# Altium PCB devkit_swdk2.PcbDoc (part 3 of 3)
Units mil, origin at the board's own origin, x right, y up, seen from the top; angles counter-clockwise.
Board outline 2700 x 2100 mil, 4 copper layers (Component Side, Internal Plane 1, Internal Layer 2, Bottom Layer), stack 57.8 mil thick; 223 components, 143 nets, 656 pads, 485 vias.
Unrouted connection lines stored in the file: 72.
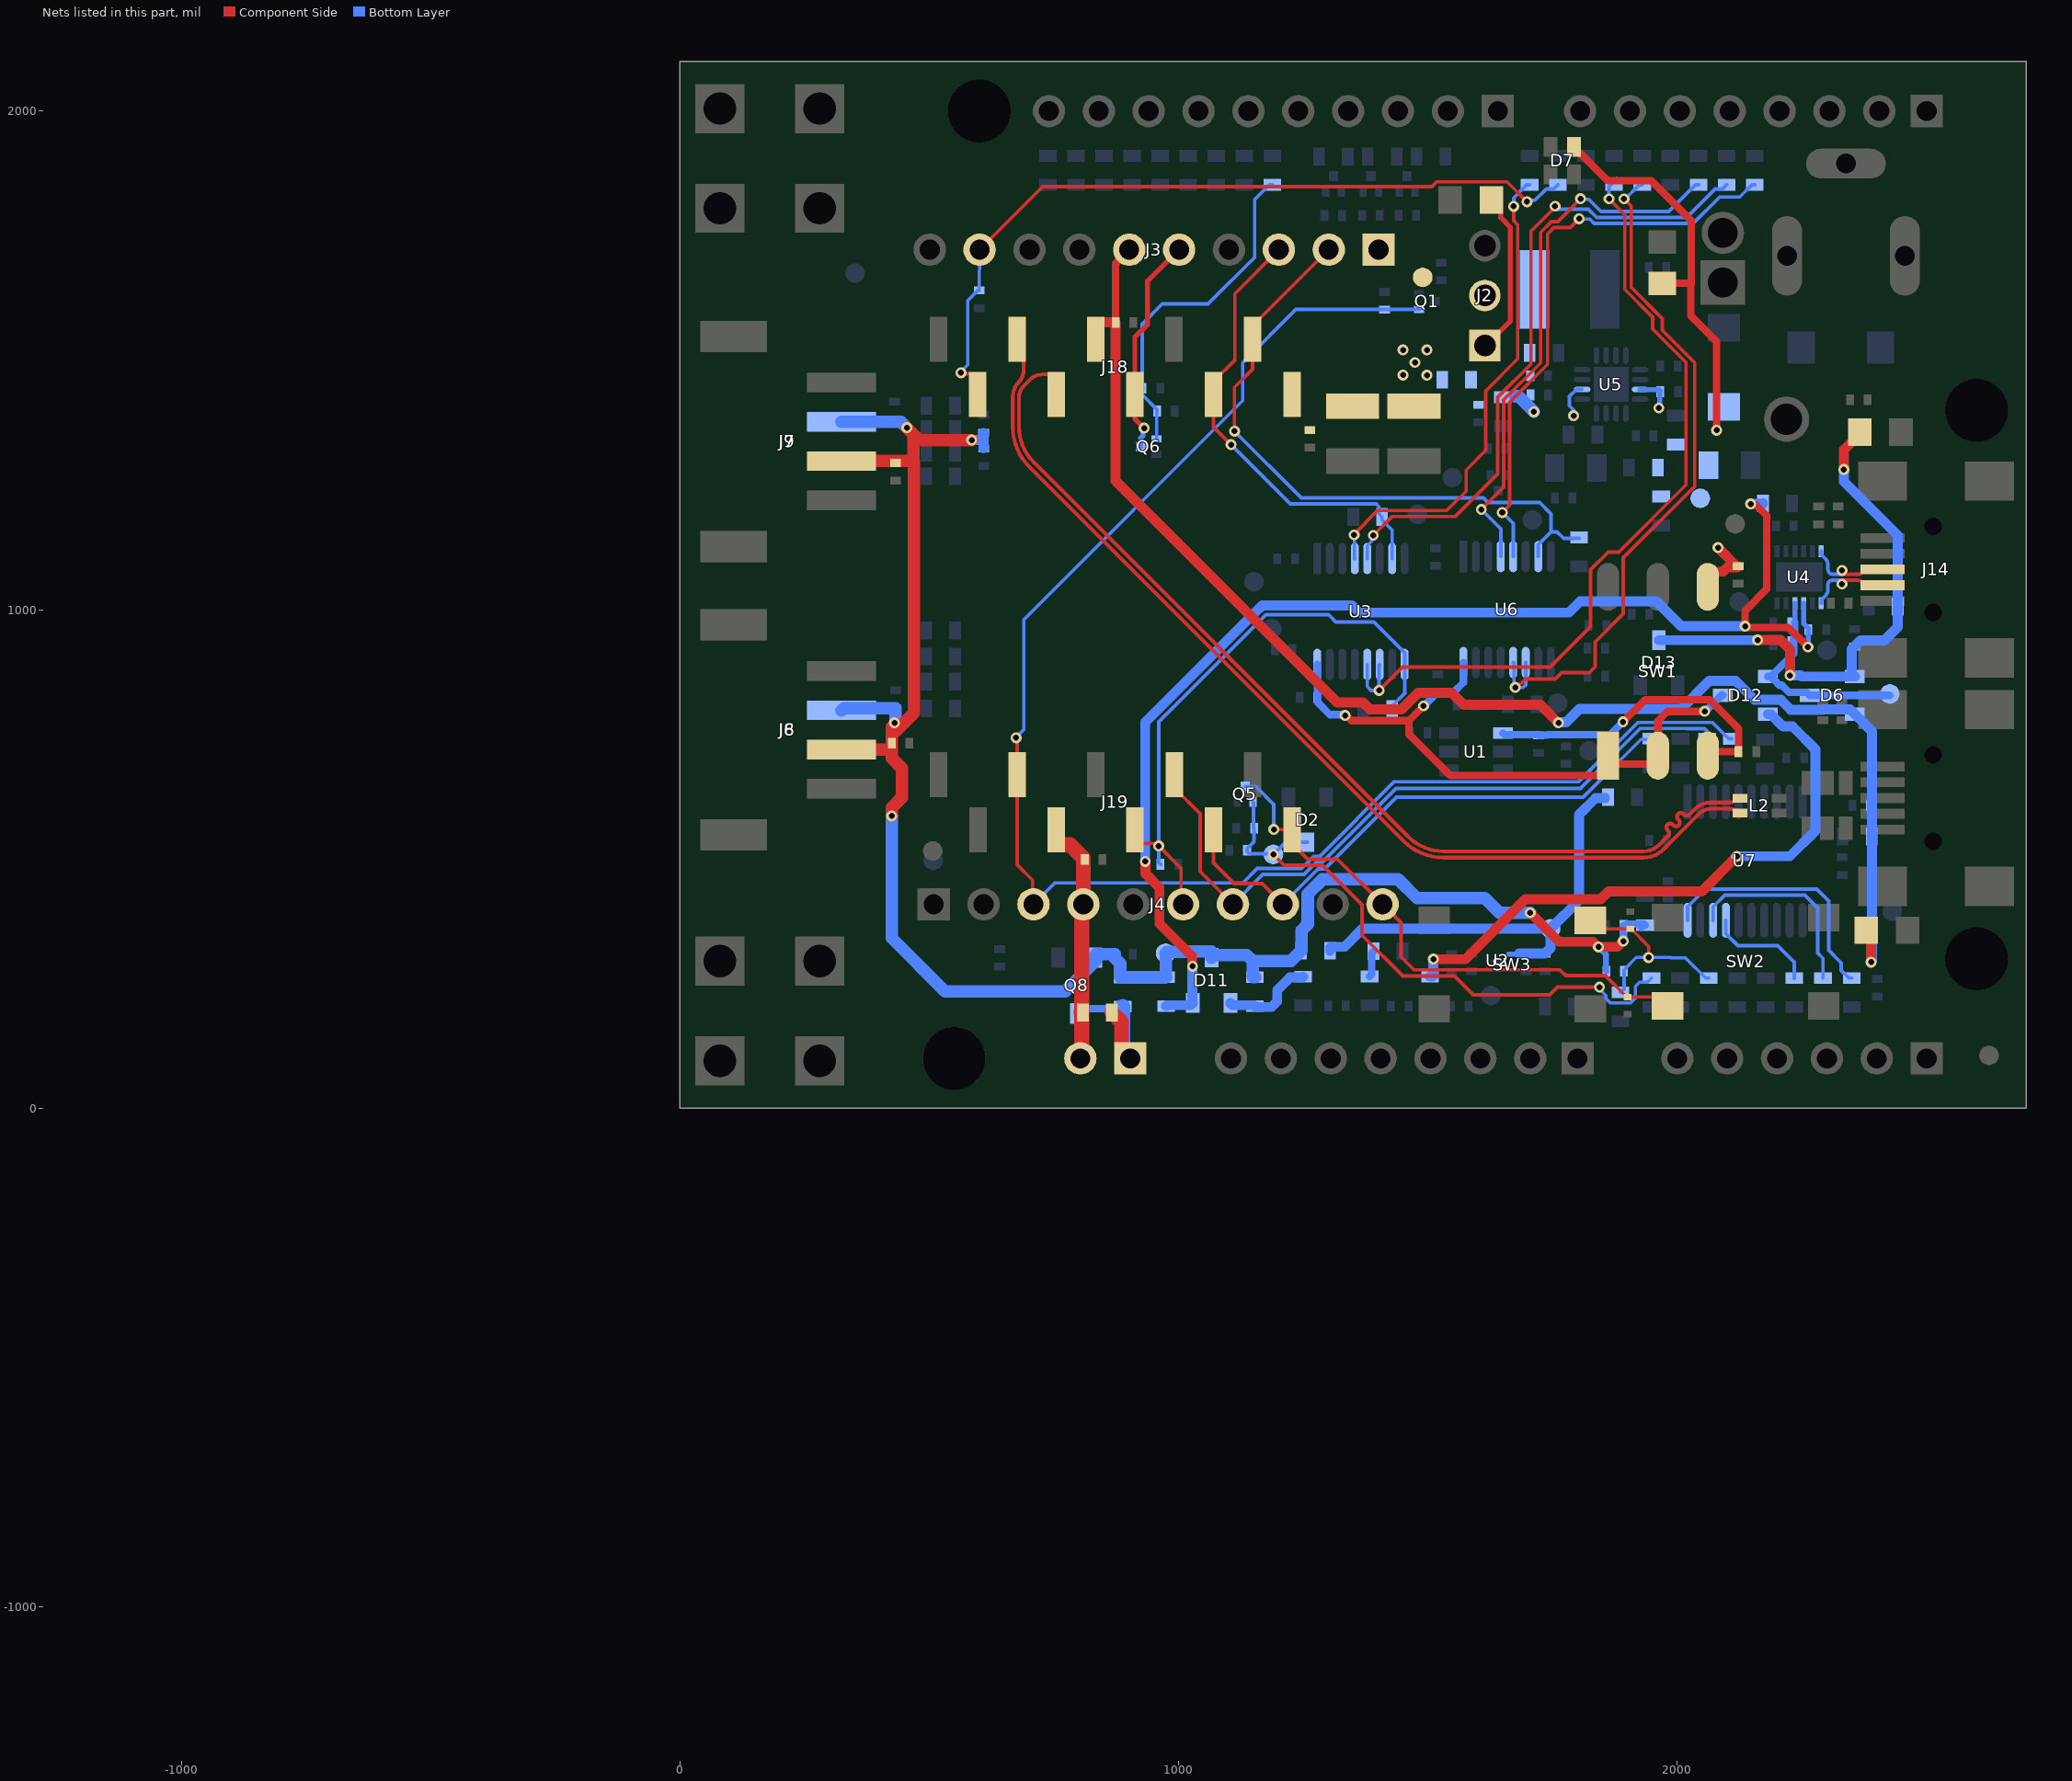
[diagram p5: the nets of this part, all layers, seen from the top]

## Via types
v1: diameter 22, hole 12, Component Side to Bottom Layer, 485 vias

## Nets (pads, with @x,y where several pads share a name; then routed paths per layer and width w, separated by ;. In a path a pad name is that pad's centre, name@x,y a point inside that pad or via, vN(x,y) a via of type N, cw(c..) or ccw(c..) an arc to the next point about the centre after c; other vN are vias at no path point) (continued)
SKY_CTS_ARD: SB19.2 U6.11 U6.12 | length 1425.2
  Component Side w7: v1(1675,844) 1678.41,844 1695.41,861 1755.02,861 1768.02,874 1823.58,874 1835,885.42 1835,935 1891.74,991.74 1891.74,1104.24 2035,1247.5 2035,1495.42 1970,1560.42 1970,1584 1907.5,1646.5 1907.5,1809.5 v1(1893,1824)
  Bottom Layer w7: U6.12@1671,893.92 1672.67,892.25 1672.67,846.33 v1(1675,844) 1691,844 1696,849 U6.11@1696,893.92 ; v1(1893,1824) 1895.73,1824 1923.74,1852.01 SB19.2@1929.64,1852.01
SKY_DIN: J3.3 J18.3 SB48.1 U3.7 | length 923.2
  Component Side w7: v1(1105,1331) 1069.83,1366.17 J18.3@1069.83,1431.81 1069.83,1457.83 1113,1501 1113,1634 J3.3@1201,1722
  Bottom Layer w7: v1(1105,1331) 1223.78,1212.22 1396.34,1212.22 1401.39,1207.17 1401.39,1192.61 SB48.1@1408,1186 1408,1180.09 1428.25,1159.84 U3.7@1428.25,1102.68
SKY_DIO2: J4.8 J19.8 SB45.1 | length 1130.9
  Component Side w7: J19.8@1070,558.74 1070,492 1111.5,450.5 1167.5,450.5 J4.8@1209,409
  Bottom Layer w7: J4.8@1209,390 1209,390.41 J4.8@1218.3,399.7 ; J4.8@1209,409 1209,409.41 1279.59,480 1293,480 1437,624 1811.42,624 1926.92,739.5 1946.23,739.5 SB45.1@1948.25,741.52
SKY_DIO2_VREF: SB29.1 U7.20 | length 511.9
  Bottom Layer w7: U7.20@2020.6,377 2020.6,404 2056.2,439.6 2279.45,439.6 2303.5,415.55 2303.5,316.77 2328.78,291.49 2328.78,276.31 2344.09,261 SB29.1@2350,261
SKY_DIO3: J4.7 J19.7 SB46.1 | length 1456.7
  Component Side w7: J19.7@991.26,668.98 991.26,642.74 1043,591 1043,475 J4.7@1109,409 J4.7@1109,390
  Bottom Layer w7: J4.7@1109,409 1168.81,468.81 1251.44,468.81 1274.62,492 1286.5,492 1436,641.5 1805.5,641.5 1925.83,761.83 2018.63,761.83 2019.15,761.31 2054.73,761.31 2063.63,752.41 SB46.1@2063.63,741 ; SB46.1@2059.58,741 SB46.1@2063.63,741 ; SB46.1@2063.63,732.17 SB46.1@2063.63,741
SKY_DIO3_VREF: SB28.1 U7.18 | length 402.5
  Bottom Layer w7: U7.18@2071.8,377 2071.8,404 2095.4,427.6 2255.9,427.6 2281.5,402 2281.5,311.5 2292.25,300.75 SB28.1@2292.25,261
SKY_DOUT: J3.2 J18.2 SB49.1 U6.7 | length 1276.7
  Component Side w7: v1(1112,1358) 1112,1446 1148.57,1482.57 J18.2@1148.57,1542.05 ; J18.2@1148.57,1569.61 J3.2@1301,1722
  Bottom Layer w7: v1(1112,1358) 1245.78,1224.22 1611.36,1224.22 1620.58,1215 1724,1215 1747,1192 1747,1156.14 ; U6.7@1721,1106.52 1721,1130.14 1747,1156.14 ; SB49.1@1803.5,1143 1772.14,1143 1759,1156.14 1747,1156.14
SKY_DTR: J3.9 J18.9 R6.2 SB16.2 | length 1580.2
  Component Side w7: v1(563.5,1475) 565.11,1473.39 583.37,1473.39 597.39,1459.37 J18.9@597.39,1431.81 ; J3.9@601,1722 727.5,1848.5 1507.81,1848.5 1517.37,1858.06 1658.64,1858.06 v1(1698.51,1818.19)
  Bottom Layer w7: v1@563.5,1477.5 577,1491 577,1619.97 597.2,1640.18 R6.2@600.15,1640.18 J3.9@601,1722 ; v1(1698.51,1818.19) 1701.38,1821.06 1714.61,1821.06 1737.24,1843.7 1752.1,1843.7 SB16.2@1760.41,1852.01 ; J3.9@601,1722 ccw(c603.04,1719.96) 600.15,1719.96 cw(c603.04,1719.96) J3.9@601,1722
SKY_NRESET: J3.5 J18.5 Q6.3 | length 442.8
  Component Side w10: v1(931,1364) 912.35,1382.65 J18.5@912.35,1431.81 912.35,1546.48 938,1572.14 938,1659 J3.5@1001,1722
  Bottom Layer w10: Q6.3@924.25,1327 923.63,1327.63 923.63,1344 928.7,1349.08 928.7,1361.7 v1(931,1364)
Sky_ON_OFF_SW: C40.1 D2.3 Q5.1 R56.2 SB24.1 TP7.1 | length 1212.3
  Component Side w7: v1(1190,509) 1211.5,487.5 1288.48,487.5 1368,407.98 1368,347 1450,265 1553.11,265 1590.61,227.5 1744.08,227.5 1759.58,243 v1(1844,243)
  Bottom Layer w7: Q5.1@1149,614 1150.09,612.91 1150.09,562.84 R56.2@1151.18,561.75 1151.18,534.53 1137.26,520.61 C40.1@1137.26,517.65 1137.26,514.7 1141.63,510.33 1182.33,510.33 1185.5,513.5 v1(1190,509) 1214.45,533.45 D2.3@1258.21,533.45 ; v1(1844,243) 1844,238.94 1856.77,226.17 1856.77,220.18 1865.5,211.45 1906.5,211.45 1916,220.95 1916,244.5 1924.19,252.69 1939.94,252.69 SB24.1@1948.25,261
SKY_ONOFF: D14.K J4.10 J19.10 Q5.3 SW2.2 | length 1115.1
  Component Side w7: v1(1191,559) 1227.22,559 J19.10@1227.48,558.74 1227.48,531.18 1259.16,499.5 1318.5,499.5 J4.10@1409,409 1445.9,372.1 1445.9,303.52 1471.7,277.72 1764.39,277.72 1776,266.12 1855.63,266.12 1898.52,223.22 1962.7,223.22 SW2.2@1980.5,205.42
  Bottom Layer w7: Q5.3@1133.25,645.5 1154.5,645.5 1191,609 v1(1191,559)
SKY_ONSLEEP: J4.3 J19.3 Q1.1 R23.2 SB47.1 | length 3269.9
  Component Side w7: v1(674,743) 676.3,740.7 J19.3@676.3,668.98 676.3,488.2 707,457.5 707,392 J4.3@709,390
  Bottom Layer w7: v1@674,744 689.5,759.5 689.5,980.05 1128.52,1419.07 1128.52,1495.52 1235.25,1602.25 Q1.1@1482.25,1602.25 ; J4.3@709,409 752,452 1129,452 1157.81,480.81 1246.46,480.81 1270.91,505.26 1282.79,505.26 1432.53,655 1802.03,655 1920.86,773.83 2070.27,773.83 2103.09,741 SB47.1@2109,741
SKY_ONSLEEP_VREF: SB27.1 U7.17 | length 219.8
  Bottom Layer w7.55: U7.17@2097.4,377 2097.4,350 2121.56,325.84 2201.66,325.84 2234.75,292.75 SB27.1@2234.75,261
SKY_RESET: C47.1 Q6.1 R21.2 SB14.2 | length 688.3
  Bottom Layer w7: R21.2@927.82,1444.15 927.5,1443.83 R21.2@927.5,1443.65 ; Q6.1@955.75,1342.75 956.25,1343.25 956.25,1397.85 C47.1@956.74,1398.35 956.74,1401.3 927.5,1430.54 R21.2@927.5,1443.65 ; SB14.2@1188,1852.19 1182.09,1852.19 1152.5,1822.6 1152.5,1706.5 1059.15,1613.15 967.15,1613.15 927,1573 927,1444.15 R21.2@927.5,1443.65
SKY_RTS: J4.6 J19.6 R7.2 SB50.1 U3.9 | length 1264.2
  Component Side w7: J19.6@912.52,558.74 912.52,531.18 954.82,531.18 v1(960,526) 1004.87,481.13 1004.87,394.13 J4.6@1009,390
  Bottom Layer w7: R7.2@963.82,489.15 960,492.98 v1(960,526) 960,774.95 1160.55,975.5 1160.77,975.5 1175.33,990.05 1300.95,990.05 1315.5,975.5 1391.46,975.5 1453.25,913.71 U3.9@1453.25,890.08 1453.25,832.01 1428.15,806.91 SB50.1@1428.15,801 ; J4.6@1004.55,394.45 J4.6@1009,390
SKY_RTS_ARD: SB18.2 U3.11 U3.12 | length 1661.1
  Component Side w7: v1(1402,838) 1449,885 1745.08,885 1826,965.92 1826,1080.1 1861.4,1115.5 1882.58,1115.5 2017.5,1250.42 2017.5,1495.95 1950.5,1562.95 1950.5,1586.53 1894.81,1642.22 1894.81,1792.19 v1(1863,1824)
  Bottom Layer w7: U3.12@1378.25,890.08 1378.25,845.75 1386,838 v1(1402,838) 1402,888.83 U3.11@1403.25,890.08 ; v1(1863,1824) 1863,1848.5 1878.5,1864
SKY_USB_N: J18.8 L2.2 | length 2244.6
  Component Side w7.6: J18.8@689,1498 689,1478.64 ; 1451.51,535.67 700.35,1286.83 ; L2.2@2125.63,592.43 L2.2@2125.63,592.43 cw(c2125.57,606.54) 2115.59,596.57 ccw(c2105.61,586.59) 2105.61,600.7 2067.42,600.7 ccw(c2067.42,567.58) 2044,591 1987.5,534.5 1972.19,519.19 cw(c1932.38,558.99) 1932.38,502.7 1531.08,502.7 ; 667.4,1366.38 ccw(c779.9,1366.38) 700.35,1286.83 ; 667.4,1366.38 ccw(c779.9,1366.38) 700.35,1286.83 ; 667.4,1366.38 667.4,1426.49 ; 667.4,1426.49 cw(c711.2,1426.49) 680.23,1457.46 ; 667.4,1426.49 cw(c711.2,1426.49) 680.23,1457.46 ; 680.23,1457.46 ccw(c659.05,1478.64) 689,1478.64 ; 680.23,1457.46 ccw(c659.05,1478.64) 689,1478.64 ; 1531.08,502.7 cw(c1531.08,615.2) 1451.53,535.65 ccw(c1531.08,615.2) 1531.08,502.7
SKY_USB_P: J18.7 L2.1 | length 2239.9
  Component Side w7.6: J18.7@744.03,1457.97 744.03,1469.11 741.15,1472 728,1472 ; L2.1@2125.63,621.57 L2.1@2125.63,621.57 ccw(c2125.57,607.46) 2115.59,617.43 cw(c2105.61,627.41) 2105.61,613.3 2067.37,613.3 ccw(c2067.37,567.7) 2035.06,599.88 2029.69,594.51 2024.31,589.13 cw(c2018.94,594.51) 2013.56,589.13 2012.47,590.22 ccw(c2007.1,584.85) 2001.72,590.22 ccw(c2007.1,584.85) 2001.72,579.47 2002.82,578.38 cw(c1997.44,573.01) 2002.82,567.64 cw(c1997.44,573.01) 1992.07,567.64 1990.98,568.73 ccw(c1985.6,563.35) 1980.23,568.73 ccw(c1985.6,563.35) 1980.23,557.98 1981.32,556.89 cw(c1975.95,551.51) 1981.32,546.14 1978.59,543.41 1963.38,528.2 cw(c1932.24,559.34) 1932.24,515.3 1531.12,515.3 ; 680,1366.42 ccw(c780,1366.42) 709.29,1295.71 ; 680,1366.42 ccw(c780,1366.42) 709.29,1295.71 ; 680,1366.42 680,1426.47 cw(c711.26,1426.47) 689.16,1448.57 701.69,1461.1 ; 701.69,1461.1 cw(c728,1434.79) 728,1472 ; 701.69,1461.1 cw(c728,1434.79) 728,1472 ; 709.29,1295.71 1460.41,544.59 ; 1460.41,544.59 ccw(c1531.12,615.3) 1531.12,515.3 ; 1460.41,544.59 ccw(c1531.12,615.3) 1531.12,515.3
SKY_VREF: C24.1 J1.2 J4.4 J19.4 R3.1 | length 498.2
  Component Side w30: J19.4@755.04,558.74 755.04,531.18 757.56,528.66 782.23,528.66 809,501.9 809,409.26 808.74,409 808.74,390.26 809,390 806,387 806,103 J1.2@803,100
UART_RX1: SB23.2 U6.5 | length 1157.9
  Component Side w7: v1(1649,1195) 1664,1210 1664,1416.06 1739.85,1491.91 1739.85,1753.68 1752.53,1766.36 1785.36,1766.36 v1(1803,1784)
  Bottom Layer w7: v1(1649,1195) 1671,1173 U6.5@1671,1106.52 ; v1(1803,1784) 1803.47,1783.53 1824.5,1783.53 1833.53,1774.5 2031.87,1774.5 2085.19,1827.81 2125.19,1827.81 2149.38,1852.01 SB23.2@2155.28,1852.01
UART_RX2: SB21.2 U6.4 | length 1092.4
  Component Side w7: v1(1607,1201) 1652,1246 1652,1421.03 1725.83,1494.86 1725.83,1756.64 1747.7,1778.5 1760.43,1778.5 v1(1806.13,1824.2)
  Bottom Layer w7: v1(1607,1201) 1646,1162 U6.4@1646,1106.52 ; v1@1806.13,1823 1822.36,1823 1846.86,1798.5 1983.05,1798.5 2036.56,1852.01 SB21.2@2042.46,1852.01
UART_TX1: SB22.2 U3.5 | length 1317.1
  Component Side w7: v1(1390.36,1149) 1428.36,1187 1555,1187 1640,1272 1640,1426 1706.5,1492.5 1706.5,1758.92 1755,1807.42 v1(1755,1809.19)
  Bottom Layer w7: U3.5@1378.25,1102.68 1378.25,1128.67 1387.49,1137.91 1387.49,1146.13 v1(1390.36,1149) ; v1(1755,1809.19) 1760.69,1803.5 1821.5,1803.5 1838.5,1786.5 2018.5,1786.5 2075.7,1843.7 2090.56,1843.7 SB22.2@2098.87,1852.01
UART_TX2: SB15.2 U3.4 | length 986.9
  Component Side w7: v1(1352,1150) 1352,1151.58 1399.42,1199 1538,1199 1576.5,1237.5 1576.5,1280 1616,1319.5 1616,1437.97 1618,1439.97 1618,1441 1680,1503 1680,1772 1672,1780 v1(1672,1809)
  Bottom Layer w7: v1(1352,1150) 1352.63,1149.37 1352.63,1103.31 U3.4@1353.25,1102.68 ; v1(1672,1809) 1672,1825.91 1698.09,1852.01 SB15.2@1704,1852.01
USB_N: J14.2 U4.1 | length 173.6
  Component Side w7: v1(2330,1051.3) 2330,1058 2330.87,1058.87 2360.34,1058.87 cw(c2360.34,1042.23) 2366.35,1057.74 cw(c2360.34,1042.23) 2372.11,1053.99 ccw(c2383.88,1065.76) 2383.88,1049.12 J14.2@2411.43,1049.12
  Bottom Layer w7: U4.1@2288.72,1012.83 2288.72,1019.72 2297.06,1028.06 ccw(c2285.12,1040) 2302,1040 2302,1050 cw(c2311,1050) 2311,1059 2329.47,1059 2330,1058.47 v1(2330,1051.3)
USB_P: J14.3 U4.12 | length 171.3
  Component Side w7: v1(2330,1078.55) 2330,1072 2331.13,1070.87 2360.34,1070.87 ccw(c2360.34,1087.51) 2366.35,1071.99 ccw(c2360.34,1087.51) 2372.11,1075.74 cw(c2383.88,1063.97) 2383.88,1080.61 J14.3@2411.43,1080.61
  Bottom Layer w7: U4.12@2288.72,1117.17 2288.72,1110.28 2297.07,1101.93 cw(c2285.12,1090) 2302,1090 ; 2302,1088 2302,1081 ccw(c2312,1081) 2312,1071 2330,1071 v1(2330,1078.55)
User_Button: C39.1 D15.K R32.2 SB53.1 SW3.2 | length 406
  Component Side w7: SW3.2@1825.5,376.58 1842.3,359.78 1907.48,359.78 1942.5,324.75 v1(1942.5,302.5)
  Bottom Layer w7: C39.1@1886,232.5 1893.18,239.68 R32.2@1893.18,274.85 1893.18,277.8 1917.88,302.5 v1(1942.5,302.5) 1986.58,302.5 1987.58,301.5 2016.34,301.5 2056.84,261 SB53.1@2062.75,261
VCC_1V8: C37.1 C38.1 SB31.1 SB43.1 TP11.1 U2.1 | length 902.8
  Bottom Layer w10: U2.1@1661.06,308.8 1681.54,308.8 1683,310.26
  Bottom Layer w20: SB31.1@1303.63,316 1303.63,321.91 SB31.1@1303.73,322 ; SB31.1@1303.63,322.09 SB31.1@1303.73,322 ; SB31.1@1305.44,320.28 SB31.1@1303.73,322 ; 1683,310.26 C37.1@1696.85,310.26 C38.1@1734.85,310.26 1746,321.41 TP11.1@1746,360 1803,417 1803,589.11 1835.59,621.69 1835.59,622 SB43.1@1855,622 ; TP11.1@1734.92,360 1368.84,360 1332.55,323.72 1305.44,323.72 SB31.1@1303.73,322
VCC_3V3_FTDI: C16.1 D11.2 SB1.1 SB32.1 U4.3 | length 2534.7
  Component Side w15: v1(2147,1212) 2148.34,1210.66 2157.57,1210.66 2179.5,1188.73 2179.5,1041.27 2135.88,997.65 v1(2135.88,966.8) 2138.18,964.5 2222.5,964.5 2260,927 v1@2261,927
  Component Side w20: v1(933,495) 933.38,494.62 933.38,470.62 961.5,442.5 961.5,370.32 1027,304.82 v1@1027,286
  Bottom Layer w10: U4.3@2253.28,1012.83 2253.28,972.26 2262.3,963.24 C16.1@2262.3,954.39 ; v1(2262,925) 2262.37,925.37 2262.37,954.02 C16.1@2262.52,954.17
  Bottom Layer w20: v1(933,495) 933,774.12 1152.88,994 1153.11,994 1167.66,1008.55 1347.45,1008.55 1362,994 1453.74,994 1473.77,994 1782.68,994 1805.35,1016.67 1957.76,1016.67 2007.64,966.8 v1(2135.88,966.8) ; SB32.1@975,205 976.81,206.81 1024.42,206.81 1028.2,210.59 D11.2@1028.2,211.45 1027.38,212.27 v1@1027.38,285.62 ; v1(2147,1212) 2147.38,1212.38 2171.38,1212.38 SB1.1@2172,1213
  other v1: 1028,285
VCC_4V0: C9.1 C10.1 C11.1 C22.1 C43.1 C44.1 D1.1 J2.1 L1.2 R4.1 R33.2 SW1.4 U5.7 U5.14 | length 675.7
  Component Side w10: J2.1@1616,1529 1665,1578 1665,1767 1645.81,1786.19 1645.81,1803.38 D1.1@1627.18,1822
  Component Side w20: SW1.4@2061,1045.83 2061,1064.99 2072.31,1076.31 2091.47,1076.31 2100.3,1085.13 2121.33,1085.13 2122.15,1085.96 C43.1@2122.15,1087.26 2118.74,1087.26 v1(2081.5,1124.5)
  Bottom Layer w7: v1(1792,1389) 1792,1400.87 1783.89,1408.98 1783.89,1427.8 1797.77,1441.69 U5.14@1809.12,1441.69
  Bottom Layer w10: U5.7@1925.26,1441.69 1925.46,1441.49 1963.13,1441.49 1966,1438.62 R33.2@1966,1437.15 1964.5,1435.65 1964.5,1406 v1(1963,1404.5)
  Bottom Layer w25: 1675.5,1428 1681.5,1428 v1(1712.5,1397)
VCC_4V0_Modem: C1.1 C2.1 C3.1 J2.2 J3.1 J18.1 R4.2 TP14.1
  other v1: 1450,1470.5 1498,1470 1474,1495.75 1450,1521 1498,1521
VCC_5V0_MUX: C41.1 C42.1 D12.3 SW1.1 SW1.2 U3.16 U6.16 | length 1262.9
  Component Side w15: v1(1334,788) 1335.89,788 1346.39,777.5 1461.5,777.5 ; v1(1491,807) 1461.5,777.5 ; v1(2055,796) 1980.5,796 1961,776.5 SW1.2@1961,707.25 1961,703.62 1947.38,690 1861,690 1861,681.74 1846.26,667 1545.06,667 1461.5,750.56 1461.5,777.5
  Bottom Layer w15: U3.16@1278.25,890.08 1278.25,814.75 1303.66,789.34 1332.66,789.34 v1(1334,788) ; v1(1491,807) 1491,806.37 1491.21,806.16 C42.1@1519.47,834.43 ; C42.1@1519.85,834.8 C42.1@1519.47,834.43 ; U6.16@1571,893.92 1571,854 1551.43,834.43 C42.1@1519.47,834.43 ; v1(2055,796) 2056.8,796 2090,829.2 D12.3@2091,828.2
VCC_ARD_3V3: SB3.1 SB42.1 | length 53.7
  Bottom Layer w15: SB3.1@1383.03,264.57 1387.02,268.56 1387.02,311.02 SB42.1@1391,315
VCC_ARD_5V0: D12.2 SB4.1 | length 1198
  Component Side w20: v1(1511,299) 1575.23,299 1695.37,419.14 1846.14,419.14 1862,435 2049,435 v1(2119.5,505.5)
  Bottom Layer w20: SB4.1@1504,264.57 1508.81,264.57 1510.62,266.38 1510.62,298.62 v1(1511,299) ; v1(2119.5,505.5) 2225.82,505.5 2277.05,556.73 2277.05,719.89 2231.32,765.62 2212.38,765.62 2212,766 ; D12.2@2181.55,790.41 2187.46,790.41 2209.87,768 2210,768
VCC_ARD_IOREF: D11.1 SB2.1 SB33.1 | length 188.1
  Bottom Layer w20: D11.1@1103.8,211.45 1103.8,210.47 1107.58,206.69 1151.19,206.69 SB33.1@1153,204.88 1154.81,203.07 1186.06,203.07 1197.78,214.78 1197.78,236.91 1223.06,262.19 1247.82,262.19 SB2.1@1249.63,264
VCC_FTDI_USB: C14.1 D3.1 D6.1 D13.3 FB3.2 | length 1067.4
  Component Side w20: v1(2161,939) 2206.77,939 2226,919.77 v1(2226,868) ; v1(2334,1281) 2334.38,1281.38 2334.38,1320.78 2365.66,1352.06 D3.1@2365.66,1356
  Bottom Layer w20: D13.3@1963,938.81 1963.1,938.9 2160.9,938.9 v1(2161,939) ; v1(2226,868) 2247.45,868 2249.45,866 D6.1@2353.59,866 ; v1@2334,1279 2334,1257 2442,1149 FB3.2@2442,1006 2442,965 2415.3,938.3 2367.3,938.3 2349.81,920.81 2349.81,869.78 D6.1@2353.59,866 ; D6.1@2356,866 D6.1@2353.59,866
VCC_SKY_VREF: J1.1 Q8.3 R3.2 SB52.2 | length 317.7
  Component Side w30: R3.2@866,192 866.47,192 885.5,172.97 885.5,117.5 J1.1@903,100
  Bottom Layer w15: Q8.3@796,189.9 796,193.41 802.28,199.69 883.69,199.69 SB52.2@888,204
  Bottom Layer w30: SB52.2@888,204 888,115 J1.1@903,100
VCC_SKY_VUSB: C23.1 C25.1 D6.2 D9.1 FB2.1 J3.6 J18.6 | length 2912.9
  Component Side w15: J18.6@833.61,1542.05 J18.6@833.61,1566.13 ; C23.1@873.74,1576.15 873.74,1694.74 J3.6@901,1722 ; D9.1@2369.34,366.66 D9.1@2379,357
  Component Side w20: J18.6@833.61,1566.13 833.61,1568.63 841.13,1576.15 C23.1@873.74,1576.15 873.74,1258.49 1318.23,814 1369.75,814 1383.75,800 1447.23,800 1480.23,833 1547.48,833 1571.48,809 1725.5,809 v1(1761.5,773) ; D9.1@2379,357 2388.44,347.56 2388.44,293.38 v1(2388.82,293)
  Bottom Layer w20: v1(1761.5,773) 1762.5,774 1777,774 1804,801 2008.22,801 2064.2,856.98 2116.9,856.98 2154.69,819.19 2207.45,819.19 2227.22,799.42 2291.35,799.42 2291.92,800 2346.41,800 D6.2@2356,790.41 2390.43,755.98 FB2.1@2390.43,545 ; v1(2388.82,293) 2388.82,295.82 2390.43,297.43 FB2.1@2390.43,545 ; FB2.1@2389.82,545 FB2.1@2390.43,545
VCC_TPL: C4.1 C46.1 SW1.3 U1.1 | length 639.1
  Component Side w10: SW1.3@2061,707.25 SW1.3@2068.9,715.15
  Component Side w15: v1(1891,775) 1935.5,819.5 2064.73,819.5 2122.74,761.49 C46.1@2122.74,715.15 SW1.3@2068.9,715.15
  Bottom Layer w15: U1.1@1650.42,752.4 1653.32,749.5 1721.85,749.5 1723.35,748 1723.98,748.63 1739.4,748.63 1740.27,749.5 1865.5,749.5 v1(1891,775)
VCC_USB: C5.1 C6.1 D6.3 D12.1 TP1.1 U4.4 | length 419.4
  Bottom Layer w10: C5.1@2235.26,975.15 2235.49,975.39 2235.49,1012.76 U4.4@2235.57,1012.83
  Bottom Layer w15: D12.1@2181.55,866 2187.46,866 2233.12,911.66 2233.12,939.64 C6.1@2234.48,941 ; D12.1@2192,859.72 2193.74,859.72 2205.11,848.34 2210.12,848.34 2223.98,834.48 2259.17,834.48 D6.3@2265.45,828.2 TP1.1@2426,828.2 ; C6.1@2235.26,941 C5.1@2235.26,975.15
VCC_VIN: C7.1 C34.1 D4.1 D5.K D7.4 FB1.1 SB5.1 TP12.1 | length 796.8
  Component Side w15: D7.4@1793,1928 1860.5,1860.5 1947.5,1860.5 2028,1780 2028,1654 2027.34,1654.66 ; D4.1@1969.89,1654.66 2027.34,1654.66 ; v1(2079,1359.94) 2079,1538 2027.34,1589.66 2027.34,1654.66
VCC_VREF: C17.1 C18.1 C19.1 C20.1 C45.1 D11.3 J6.2 J7.2 J8.2 J9.2 Q8.2 R32.1 R35.2 R54.2 R55.2 SB31.2 SB32.2 SB33.2 SB44.2 SB52.1 TP13.1 | length 3812.6
  Component Side w20: v1(1705,392) 1762.98,334.02 1830.94,334.02 1841.46,323.5 v1(1842,323.5) 1842.38,323.88 1879.84,323.88 1890.96,335 v1(1891.5,335)
  Component Side w25: J6.2@324,719.52 424.74,719.52 ; J7.2@324,1298 468.5,1298 ; v1(424.74,586.41) 424.74,602.74 445,623 445,681.96 424.74,702.22 424.74,719.52 ; 431.69,755.54 469,792.85 469,1297.5 468.5,1298 ; v1@431.69,771.54 424.74,764.59 C18.1@424.74,732.15 424.74,719.52 ; v1(455,1365) 468.5,1351.5 ; v1(585,1340) 480,1340 468.5,1351.5 ; 468.5,1298 468.5,1351.5
  Bottom Layer w12: v1(1842,323.5) 1856.59,308.91 1856.59,276 R32.1@1857.74,274.85
  Bottom Layer w15: v1(1891.5,335) 1892.07,335.57 1892.07,366.47 R35.2@1892.44,366.85 ; R35.2@1899.47,369.43 1933,369.43 SB44.2@1935.3,367.13 1931.65,367.13 SB44.2@1927.34,362.82
  Bottom Layer w20: v1(585,1340) 585.38,1340.38 606.65,1340.38 ; R55.2@608.88,1354.77 609.02,1354.63 609.02,1323.81 R54.2@609.15,1323.68
  Bottom Layer w25: J8.2@324,797.74 329,802.74 C17.1@432.15,802.74 432.15,758.92 430.24,757 ; J9.2@324,1376.96 443.04,1376.96 v1(455,1365) ; v1(424.74,586.41) 424.74,341.26 532,234 772.19,234 833.4,295.21 Q8.2@833.4,302.1 833.4,307.72 834.68,309 C45.1@872.57,309 872.57,300.98 882.78,290.77 882.78,262.69 883.47,262 SB52.1@888,262 888.5,262.5 973.5,262.5 SB32.2@974,263 ; SB32.2@975,263 SB32.2@974,263 ; D11.3@1066,302 D11.3@1066,314.5 ; SB33.2@1153,262.88 1149.38,262.88 1148.69,263.57 1148.69,295.5 ; v1(1705,392) 1643.27,392 1613.77,421.5 1477.94,421.5 1440.44,459 1288.29,459 1259,429.71 1259,369.29 1246.32,356.61 1246.32,316.69 SB31.2@1245.63,316 1225.13,295.5 1148.69,295.5 ; SB32.2@974,263 974.5,263.5 974.5,310.5 TP13.1@974,311 976.75,313.75 1014.44,313.75 1015.2,314.5 D11.3@1066,314.5 ; D11.3@1066,314.5 1073.31,307.19 1137,307.19 1148.69,295.5
  other v1: 430.24,773
pads on no net: D2.2 D10.3 D10.4 Fiducial1.Fiducial Fiducial2.Fiducial Fiducial3.Fiducial Fiducial4.Fiducial Fiducial5.Fiducial Fiducial6.Fiducial J3.7 J3.8 J5.0 J5.4 J11.8 J14.0 J14.4 J15.2 SW2.1 SW3.1 SW3.4 U7.5 U7.6 U7.7 U7.8 U7.9 U7.12 U7.13 U7.14 U7.15 U7.16

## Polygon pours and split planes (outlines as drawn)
GND on Bottom Layer "GND_L04_P066" (solid, remove dead copper, pour order 66): 45,45 45,2055 2655,2055 2655,45
VCC_VIN on Bottom Layer "VCC_VIN_L04_P038" (solid, pour order 38): 2065.8,1411 1977.61,1322.81 1949,1294.2 1949,1225 1958.28,1215.72 2049.12,1216.23 2065.06,1221.59 2128.63,1285.15 2128.63,1396.81 2114.44,1411
NetC31_1 on Bottom Layer "NETC31_1_L04_P062" (solid, pour order 62): 1864.84,1195.84 1839,1170 1839,1123.5 1846.5,1116 1985,1116 1985,1186.72 1892.53,1198.98
NetC8_1 on Bottom Layer "NETC8_1_L04_P035" (solid, pour order 35): 1887.14,1405.03 1838.14,1405.03 1822.14,1389.03 1822.14,1202.52 1822.14,1182.03 1832.27,1171.21 1870.14,1203.81 1877.9,1215.78 1880.14,1216.03 1890.14,1225.75 1901.86,1225.75 1914.14,1238.03 1914.14,1309.03 1905.14,1318.03 1905.14,1367.03 1887.14,1385.03
NetL1_1 on Bottom Layer "NETL1_1_L04_P048" (solid, pour order 48): 1884,1505 1884,1575 1883,1576 1826,1576 1826,1508 1831,1503 1882.44,1503
VCC_4V0 on Bottom Layer "VCC_4V0_L04_P050" (solid, pour order 50): 1698.47,1612.28 1574.47,1488.28 1572.97,1483.92 1572.97,1395.28 1698.78,1395.28 1738.47,1434.97 1738.47,1521.28 1742.87,1525.68 1742.87,1602.88 1733.47,1612.28
VCC_4V0_Modem on Bottom Layer "VCC_4V0_MODEM_L04_P060" (solid, pour order 60): 1427.53,1536.24 1436.68,1546.61 1535.69,1546.54 1545.96,1537.4 1545.96,1438.23 1538.84,1432 1445.16,1432 1433.49,1432 1427.67,1437.5
NetD5_A on Bottom Layer "NETD5_A_L04_P046" (solid, pour order 46): 2303,1486 2303,1758 2271,1790 2161,1790 2070,1699 2041,1699 2021,1679 2021,1502 2063,1460 2277,1460
GND on Component Side "GND_L01_P068" (solid, remove dead copper, pour order 68): 45,45 45,2055 2655,2055 2655,45
NetC31_1 on Component Side "NETC31_1_L01_P052" (solid, pour order 52): 1905,1176 1880,1204.5 1748.75,1203.75 1721,1176 1526,981 1526,932 1735,932 1905,1102
VCC_4V0_Modem on Component Side "VCC_4V0_MODEM_L01_P064" (solid, pour order 64): 1506.44,1351.5 1200,1351.5 1200,1359.51 1200,1455.48 1200,1463.31 1369.09,1628.56 1368.53,1715.79 1542.05,1714.52 1615.19,1682 1633.93,1636.87 1605.28,1600 1525.45,1554.91 1525.45,1496.25 1525.45,1369
GND on Internal Layer 2 "GND_L03_P070" (solid, remove dead copper, pour order 70): 45,45 45,2055 2655,2055 2655,45
NetC31_1 on Internal Layer 2 "NETC31_1_L03_P058" (solid, pour order 58): 1544,977.5 1503,936.5 1503,841 1523,821 1523,699 1623,599 1623,368.5 1729.5,262 1827,262 1844,279 1844,396 1762.5,477.5 1762.5,677.5 1722,718 1722,889.5 1635,976.5 1570.5,976.5
GND on Internal Plane 1 (split plane): 2649.92,50.08 50.08,50.08 50.08,2049.92 2649.92,2049.92
VCC_4V0 on Internal Plane 1 (split plane): 1954.04,1422.19 1956,1421.94 1991.87,1421.94 2063.94,1349.87 2063.94,1205 2064.19,1203.04 2064.64,1201.97 2064.95,1201.22 2066.15,1199.65 2097.44,1168.37 2097.44,1121.65 2085.5,1109.72 2071.48,1109.72 2014.56,1166.63 2014.56,1267.5 2014.31,1269.46 2013.86,1270.53 2013.55,1271.28 2012.35,1272.85 1948.85,1336.35 1947.28,1337.55 1946.53,1337.86 1945.46,1338.31 1943.5,1338.56 1766.13,1338.56 1731.35,1373.35 1729.78,1374.55 1729.03,1374.86 1727.96,1375.31 1726,1375.56 1698.56,1375.56 1698.56,1408.94 1747.31,1408.94 1754.92,1401.32 1756.49,1400.12 1758.31,1399.36 1760.27,1399.11 1897.17,1399.11 1899.13,1399.36 1900.2,1399.81 1900.95,1400.12 1902.52,1401.32 1923.63,1422.44 1953.46,1422.44

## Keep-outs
Component Side:
  the board outline again, w6
Keep-Out Layer:
  the board outline again, w6

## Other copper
Component Side:
  pour cut-out: 1987.5,663.75 2035,663.75 2035,674.25 1987.5,674.25
  pour cut-out: 1576.5,1784.5 1610.5,1784.5 1615,1789 1610,1794 1572.5,1794
  pour cut-out: 1168,2019 1546.5,2019 1546.5,2001.5 1167,2001.5
  pour cut-out: 2450,276.5 2439,287.5 2400.5,287.5
  region: -1200,-1230
  pour cut-out: 2481.96,1318.44 2481.96,1292 2505,1292
  pour cut-out: 1608.7,1594.8 1608.7,1579.2 1605,1575.5 1592,1575.5
  pour cut-out: 245.1,768.58 245.1,729.9 249,726 267,744 267,790
  pour cut-out: 245.1,1347.05 245.1,1327.68 263.89,1327.68 264,1327.57 264,1356
Bottom Layer:
  pour cut-out: 2034,1419.75 2025,1419.75 2025,1400.25 2033,1400.25
  pour cut-out: 1923,1312 1923,1303 1942.5,1303 1942.5,1311
  pour cut-out: 2204,700 2195,700 2195,725.5 2204,725.5
  pour cut-out: 1034,386 1086.5,386 1086.5,327 1146,327 1146,414.5 1033.5,414.5 1033.5,406.5
  pour cut-out: 2308.63,2020 2509.13,2020 2511.13,2018 2498.13,2005 2315.28,2005
  pour cut-out: 2209.01,2019.51 2409.51,2019.51 2411.51,2017.51 2398.51,2004.51 2215.66,2004.51
  pour cut-out: 2009.01,2019.51 2209.51,2019.51 2211.51,2017.51 2198.51,2004.51 2015.66,2004.51
  pour cut-out: 1809.01,2019.51 2009.51,2019.51 2011.51,2017.51 1998.51,2004.51 1815.66,2004.51
  pour cut-out: 1344.5,2020 1545,2020 1547,2018 1534,2005 1351.15,2005
  pour cut-out: 1144.5,2020 1345,2020 1347,2018 1334,2005 1151.15,2005
  pour cut-out: 744.5,2020 945,2020 947,2018 934,2005 751.15,2005
  pour cut-out: 2030,80 2420,80 2420,90 2020,90
  pour cut-out: 1201,1679.13 1301,1679.13 1301,1679.65 1251.13,1729.52
  pour cut-out: 1631.73,277.3 1665.59,277.3 1665.59,308.8 1654.18,308.8 1652.41,307.03
  pour cut-out: 1752.8,1730.74 1815.47,1730.74 1815.47,1541.3 1753.07,1541.3 1753.07,1542.72
  pour cut-out: 245,768 245,668 249,664 252,667 252,699
  pour cut-out: 403,1221 403,1224.85 432.15,1254 449,1254 449,1259 442,1266 439,1263 397,1263
Internal Plane 1 (plane layer: these items are gaps in the copper):
  lines w15: 1956,1429.5 1995,1429.5 2071.5,1353 2071.5,1205 2105,1171.5 2105,1118.52 2088.63,1102.15 2068.35,1102.15 2007,1163.5 2007,1267.5 1943.5,1331 1763,1331 1726,1368 1691,1368 1691,1416.5 1750.44,1416.5 1760.27,1406.67 1897.17,1406.67 1920.5,1430 1970.5,1430

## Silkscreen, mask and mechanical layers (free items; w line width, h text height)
Top Overlay:
  drawing of 1301 lines, arcs and shapes, not listed
  text "12V" at 1983,1859 h60
  text "GND" at 519.4,1765 h30 r90
  text "DTR" at 622,1765 h30 r90
  text "VUSB" at 924.1,1765 h30 r90
  text "nRESET" at 1018,1765 h30 r90
  text "GND" at 1121.4,1765 h30 r90
  text "DIN" at 1222.4,1765 h30 r90
  text "DOUT" at 1319.4,1765 h30 r90
  text "VCC" at 1421.4,1765 h30 r90
  text "ARD1 / ARD2 / Auto-ON" at 2079,1094 h50 r90
  text "www.nimbelink.com" at 659,1057 h40
  text "ON" at 1768,987 h60 r90
  text "SKYWIRE" at 782,980 h60
  text "ON / OFF" at 1460,277 h30 r90
  text "GND" at 527,273.97 h30 r90
  text "CTS" at 629,273.97 h30 r90
  text "GND" at 931,273.97 h30 r90
  text "RTS" at 1029,272.93 h30 r90
  text "DIO3" at 1133,248.98 h30 r90
  text "DIO2" at 1230,248.98 h30 r90
  text "ADC/ RING" at 1356,245 h30 r90
  text "VREF" at 835,243.98 h30 r90
  text "ON/ nSleep" at 750,189 h30 r90
  text "ON BTN" at 2342,159 h50
  text "USER SW" at 1022,157 h60
Bottom Overlay:
  drawing of 3860 lines, arcs and shapes, not listed
  text "1002583 REVB" at 1173.17,1534 h40
Mechanical 1:
  circle w11.81: c1575.32,859 r2.24
  circle w5: c600,2000 r62.99
  circle w5: c2600,300 r62.99
  circle w5: c2600,1400 r62.99
  circle w5: c550,100 r62.99
  lines w5: 0,0 0,2100 2700,2100 2700,1500 2700,0 2600,0 0,0
Drill Drawing:
  drawing of 509 lines, arcs and shapes, not listed
  text "Symbol" at -40.79,6981.94 h72
  text "Hit Count" at 465.08,6981.94 h72
  text "Finished Hole Size" at 1162.9,6981.94 h72
  text "Plated" at 2508.5,6981.94 h72
  text "Hole Type" at 3014.38,6981.94 h72
  text "1" at 465.08,6831.94 h60
  text "39.37mil (1.000mm)" at 1162.9,6831.94 h60
  text "PTH" at 2508.5,6831.94 h60
  text "Slot" at 3014.38,6831.94 h60
  text "1" at 465.08,6681.94 h60
  text "62.99mil (1.600mm)" at 1162.9,6681.94 h60
  text "PTH" at 2508.5,6681.94 h60
  text "Round" at 3014.38,6681.94 h60
  text "2" at 465.08,6531.94 h60
  text "39.37mil (1.000mm)" at 1162.9,6531.94 h60
  text "PTH" at 2508.5,6531.94 h60
  text "Slot" at 3014.38,6531.94 h60
  text "2" at 465.08,6381.94 h60
  text "60.00mil (1.524mm)" at 1162.9,6381.94 h60
  text "PTH" at 2508.5,6381.94 h60
  text "Round" at 3014.38,6381.94 h60
  text "3" at 465.08,6231.94 h60
  text "43.31mil (1.100mm)" at 1162.9,6231.94 h60
  text "PTH" at 2508.5,6231.94 h60
  text "Round" at 3014.38,6231.94 h60
  text "4" at 465.08,6081.94 h60
  text "35.43mil (0.900mm)" at 1162.9,6081.94 h60
  text "NPTH" at 2508.5,6081.94 h60
  text "Round" at 3014.38,6081.94 h60
  text "4" at 465.08,5931.94 h60
  text "125.98mil (3.200mm)" at 1162.9,5931.94 h60
  text "PTH" at 2508.5,5931.94 h60
  text "Round" at 3014.38,5931.94 h60
  text "8" at 465.08,5781.94 h60
  text "65.00mil (1.651mm)" at 1162.9,5781.94 h60
  text "PTH" at 2508.5,5781.94 h60
  text "Round" at 3014.38,5781.94 h60
  text "54" at 465.08,5631.94 h60
  text "40.00mil (1.016mm)" at 1162.9,5631.94 h60
  text "PTH" at 2508.5,5631.94 h60
  text "Round" at 3014.38,5631.94 h60
  text "485" at 465.08,5481.94 h60
  text "12.00mil (0.305mm)" at 1162.9,5481.94 h60
  text "PTH" at 2508.5,5481.94 h60
  text "Round" at 3014.38,5481.94 h60
  text "564 Total" at 465.08,5331.94 h60
  text "Slot definitions :" at -40.79,5186.97 h60
  text "Routed Path Length" at 991.9,5186.97 h60
  text "= Calculated from tool start centre position to tool end centre position." at 2094.56,5186.97 h60
  text "Hole Length" at 991.9,5086.99 h60
  text "= Routed Path Length + Tool Size = Slot length as defined in the PCB layout" at 1684.7,5086.99 h60
  text "Layer" at -67.5,4808.5 h60
  text "Name" at 342.41,4808.5 h60
  text "Material" at 1392.12,4808.5 h60
  text "Thickness" at 2251.89,4808.5 h60
  text "Constant" at 2901.72,4808.5 h60
  text "Board Layer Stack" at 3471.58,4808.5 h60
  text "NOTES:" at 5430,4710 h56.25
  text "Top Overlay" at 342.41,4688.5 h60
  text "1. BOARD IS A 1x4 ARRAY. SEE PANEL ARTWORK LAYER FOR PANEL DETAIL." at 5430,4600 h56.25
  text "Top Solder" at 342.41,4568.5 h60
  text "Solder Resist" at 1392.12,4568.5 h60
  text "1.00mil" at 2251.89,4568.5 h60
  text "3.5" at 2901.72,4568.5 h60
  text "2. BOARD TO BE SCORED AT DESIGNATED LINES. SCORING TO BE 30 DEG." at 5430,4500 h56.25
  text "1" at -67.5,4448.5 h60
  text "Component Side" at 342.41,4448.5 h60
  text "Copper" at 1392.12,4448.5 h60
  text "0.70mil" at 2251.89,4448.5 h60
  text "3. BOARD TO USE Tg 170C OR GREATER." at 5430,4400 h56.25
  text "Dielectric 1" at 342.41,4328.5 h60
  text "FR4-TG170" at 1392.12,4328.5 h60
  text "8.50mil" at 2251.89,4328.5 h60
  text "4.6" at 2901.72,4328.5 h60
  text "4. BOARD THICKNESS TOLERANCE +/- 10%." at 5430,4300 h56.25
  text "2" at -67.5,4208.5 h60
  text "Internal Plane 1" at 342.41,4208.5 h60
  text "Copper" at 1392.12,4208.5 h60
  text "1.40mil" at 2251.89,4208.5 h60
  text "5. BOARD TO USE GREEN SOLDER MASK." at 5430,4200 h56.25
  text "6. BOARD TO USE WHITE SILK SCREEN." at 5430,4100 h56.25
  text "Dielectric 3" at 342.41,4088.5 h60
  text "36.60mil" at 2251.89,4088.5 h60
  text "4.6" at 2901.72,4088.5 h60
  text "7. MIN HOLE WALL THICKNESS 1 mil." at 5430,4000 h56.25
  text "3" at -67.5,3968.5 h60
  text "Internal Layer 2" at 342.41,3968.5 h60
  text "Copper" at 1392.12,3968.5 h60
  text "1.40mil" at 2251.89,3968.5 h60
  text "8. BOARD TO USE ENIG SURFACE FINISH." at 5430,3900 h56.25
  text "Dielectric 2" at 342.41,3848.5 h60
  text "FR4-TG170" at 1392.12,3848.5 h60
  text "8.50mil" at 2251.89,3848.5 h60
  text "4.6" at 2901.72,3848.5 h60
  text "9. INNER COPPER LAYERS TO BE 1OZ COPPER. OUTER COPPER LAYERS TO BE 1/2 OZ COPPER." at 5426,3800 h56.25
  text "4" at -67.5,3728.5 h60
  text "Bottom Layer" at 342.41,3728.5 h60
  text "Copper" at 1392.12,3728.5 h60
  text "0.70mil" at 2251.89,3728.5 h60
  text "10. FOUR LAYER BOARD." at 5427,3700 h56.25
  text "Solder Side" at 342.41,3608.5 h60
  text "Solder Resist" at 1392.12,3608.5 h60
  text "1.00mil" at 2251.89,3608.5 h60
  text "3.5" at 2901.72,3608.5 h60
  text "11. BOARD TO USE 1OZ PLATING THICKNESS (1.2 mil +/-10%)." at 5427,3600 h56.25
  text "Bottom Overlay" at 342.41,3488.5 h60
  text "Fiducial" at 10835,2700 h80
  text "Fiducial" at 835,2695 h80
  text "Scrap Rail" at 8295,2285 h80
  text "V-Score" at 12543,2051 h80
  text "Copy Artwork" at 6890,1075 h80
  text "Scrap" at 6165,1059 h80 r90
  text "Scrap" at 9365,1059 h80 r90
  text "Copy Artwork" at 3881,1055 h80
  text "Copy Artwork" at 10281,1055 h80
  text "Scrap" at 2917,973 h80 r90
  text "V-Score" at 12556,-53 h80
  text "Scrap Rail" at 7220,-245 h80
  text "50 mil wide cutout" at 5505,-260 h80
  text "50 mil wide cutout" at 8605,-260 h80
  text "50 mil wide cutout" at 2367,-296 h80
  text "Fiducial" at 835,-930 h80

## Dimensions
0,2100 to 0,0 on Drill Drawing
0,-400 to 0,0 on Drill Drawing
0,-400 to 0,2500 on Drill Drawing
1000,-235 to 0,-400 on Drill Drawing
0,2500 to 12300,2500 on Drill Drawing
0,2500 to 2700,2525 on Drill Drawing
2750,2100 to 3150,2100 on Drill Drawing
0,-400 to 1040,-200 on Drill Drawing
2700,2122 to 3200,2118 on Drill Drawing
